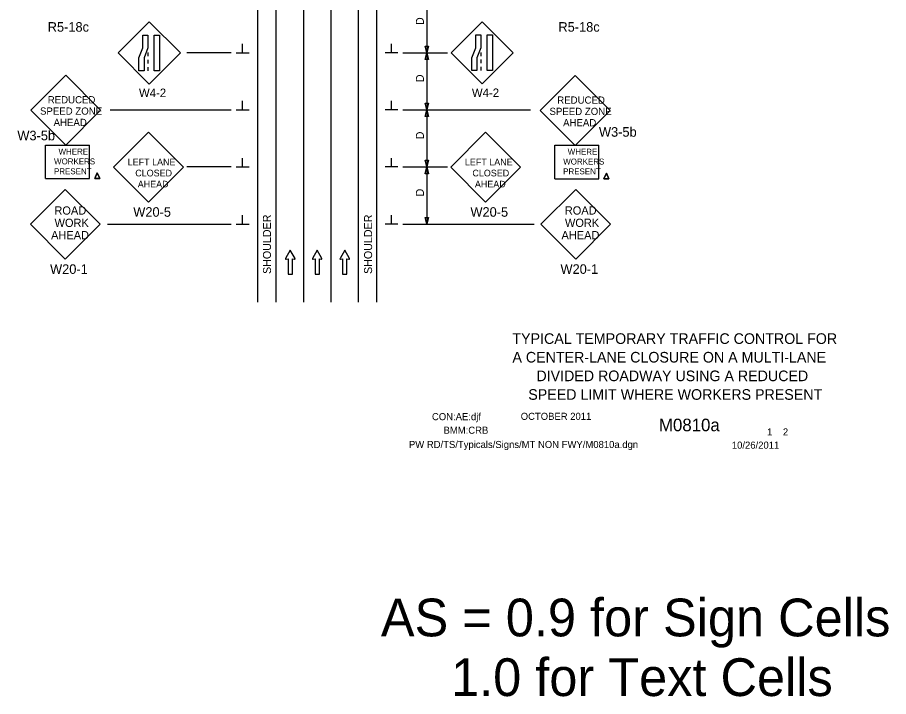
# Model space of a CAD drawing. Extents: x 16728 to 18482, y 5716 to 6919.
# Drawn here: x 16728 to 17490, y 5716 to 6311 of the extents above; entities that cross this region are included whole.
import ezdxf

# ---------------------------------------------------------------- set-up
doc = ezdxf.new("R2010")
doc.units = 0
for name, color, linetype in [('ALI_LEGAL_EX', 7, 'Continuous'), ('BORDER', 7, 'Continuous'), ('BORDER_SIGNAL_WO', 7, 'Continuous'), ('MT_SCRATCH_LEVEL_E', 7, 'Continuous'), ('PAVT_EDGE_EX', 7, 'Continuous'), ('TRAFFIC_SIGNS_PR', 7, 'Continuous'), ('TYPICAL_TEXT_DIMEN_PR', 7, 'Continuous')]:
    doc.layers.add(name, color=color, linetype=linetype)

msp = doc.modelspace()

# ---------------------------------------------------------------- linework, layer by layer
at = {"layer": 'ALI_LEGAL_EX'}
for p, q in [((16978.2, 6879.62), (16978.2, 6061.48)), ((17002.2, 6879.62), (17002.2, 6061.48))]:
    msp.add_line(p, q, dxfattribs=at)
for points in [[(16978.2, 6279.62), (16978.2, 6254.62)], [(17002.2, 6279.62), (17002.2, 6254.62)], [(16978.2, 6179.62), (16978.2, 6154.62)], [(17002.2, 6179.62), (17002.2, 6154.62)], [(16978.2, 6079.62), (16978.2, 6061.48)], [(17002.2, 6079.62), (17002.2, 6061.48)]]:
    msp.add_lwpolyline(points, dxfattribs=at)
at = {"layer": 'MT_SCRATCH_LEVEL_E'}
for p, q in [((16966.76, 6106.76), (16962.65, 6099.52)), ((16970.9, 6099.52), (16966.76, 6106.76)), ((16990.3, 6106.76), (16986.19, 6099.52)), ((16994.45, 6099.52), (16990.3, 6106.76)), ((17014.37, 6106.76), (17010.26, 6099.52)), ((17018.52, 6099.52), (17014.37, 6106.76)), ((16963.13, 6098.84), (16964.9, 6099.15)), ((16964.9, 6099.15), (16964.9, 6085.9)), ((16968.65, 6085.9), (16968.65, 6099.15)), ((16968.65, 6099.15), (16970.42, 6098.84)), ((16986.67, 6098.84), (16988.45, 6099.15)), ((16988.45, 6099.15), (16988.45, 6085.9)), ((16992.19, 6085.9), (16992.19, 6099.15)), ((16992.19, 6099.15), (16993.97, 6098.84)), ((17010.75, 6098.84), (17012.52, 6099.15)), ((17012.52, 6099.15), (17012.52, 6085.9)), ((17016.26, 6085.9), (17016.26, 6099.15)), ((17016.26, 6099.15), (17018.04, 6098.84)), ((16964.9, 6085.9), (16968.65, 6085.9)), ((16988.45, 6085.9), (16992.19, 6085.9)), ((17012.52, 6085.9), (17016.26, 6085.9))]:
    msp.add_line(p, q, dxfattribs=at)
for centre, start, end in [((16963.05, 6099.3), 150.42484, 279.96381), ((16970.49, 6099.3), 260.03619, 29.77312), ((16986.6, 6099.3), 150.42484, 279.96381), ((16994.04, 6099.3), 260.03619, 29.77312), ((17010.67, 6099.3), 150.42484, 279.96381), ((17018.11, 6099.3), 260.03619, 29.77312)]:
    msp.add_arc(centre, 0.463, start, end, dxfattribs=at)
at = {"layer": 'PAVT_EDGE_EX'}
for p, q in [((16938.2, 6879.62), (16938.2, 6061.48)), ((16954.2, 6879.62), (16954.2, 6061.48)), ((17026.2, 6879.62), (17026.2, 6061.48)), ((17042.2, 6879.62), (17042.2, 6061.48))]:
    msp.add_line(p, q, dxfattribs=at)
at = {"layer": 'TRAFFIC_SIGNS_PR'}
for p, q in [((16843.47, 6306.54), (16816.32, 6279.39)), ((16870.62, 6279.39), (16843.47, 6306.54)), ((17134.64, 6306.61), (17107.49, 6279.46)), ((17161.8, 6279.46), (17134.64, 6306.61)), ((16816.32, 6279.39), (16843.47, 6252.23)), ((16842.22, 6279.88), (16842.22, 6276.68)), ((16843.47, 6252.23), (16870.62, 6279.39)), ((17107.49, 6279.46), (17134.64, 6252.31)), ((17133.4, 6279.95), (17133.4, 6276.75)), ((17134.64, 6252.31), (17161.8, 6279.46)), ((16842.22, 6273.48), (16842.22, 6270.28)), ((17133.4, 6273.55), (17133.4, 6270.35)), ((16842.22, 6267.08), (16842.22, 6263.88)), ((17133.4, 6267.15), (17133.4, 6263.95)), ((16770.34, 6259.9), (16739.79, 6229.35)), ((16800.89, 6229.35), (16770.34, 6259.9)), ((17215.94, 6259.63), (17185.39, 6229.08)), ((17246.48, 6229.08), (17215.94, 6259.63)), ((16739.79, 6229.35), (16770.34, 6198.8)), ((16770.34, 6198.8), (16800.89, 6229.35)), ((17185.39, 6229.08), (17215.94, 6198.54)), ((17215.94, 6198.54), (17246.48, 6229.08)), ((16842.77, 6210.05), (16812.22, 6179.5)), ((16873.31, 6179.5), (16842.77, 6210.05)), ((17137.63, 6210.05), (17107.08, 6179.5)), ((17168.18, 6179.5), (17137.63, 6210.05)), ((16752.8, 6198.83), (16791.2, 6198.83)), ((16752.8, 6169.51), (16752.8, 6198.83)), ((16791.2, 6169.51), (16791.2, 6198.83)), ((17198.09, 6198.7), (17236.49, 6198.7)), ((17198.09, 6169.38), (17198.09, 6198.7)), ((17236.49, 6169.38), (17236.49, 6198.7)), ((16812.22, 6179.5), (16842.77, 6148.95)), ((16842.77, 6148.95), (16873.31, 6179.5)), ((17107.08, 6179.5), (17137.63, 6148.95)), ((17137.63, 6148.95), (17168.18, 6179.5)), ((16752.8, 6169.51), (16791.2, 6169.51)), ((17198.09, 6169.38), (17236.49, 6169.38)), ((16770.01, 6160.03), (16739.46, 6129.48)), ((16800.55, 6129.48), (16770.01, 6160.03)), ((17216.37, 6160.07), (17185.83, 6129.52)), ((17246.92, 6129.52), (17216.37, 6160.07)), ((16739.46, 6129.48), (16770.01, 6098.94)), ((16770.01, 6098.94), (16800.55, 6129.48)), ((17185.83, 6129.52), (17216.37, 6098.98)), ((17216.37, 6098.98), (17246.92, 6129.52))]:
    msp.add_line(p, q, dxfattribs=at)
for points in [[(16842.22, 6295.12), (16842.22, 6283.94), (16838.88, 6275.06), (16838.88, 6263.88), (16834.39, 6263.88), (16834.39, 6275.06), (16837.73, 6283.94), (16837.73, 6295.12)], [(16852.36, 6295.12), (16852.36, 6263.88), (16847.87, 6263.88), (16847.87, 6295.12)], [(17133.4, 6295.2), (17133.4, 6284.02), (17130.05, 6275.13), (17130.05, 6263.95), (17125.56, 6263.95), (17125.56, 6275.13), (17128.9, 6284.02), (17128.9, 6295.2)], [(17143.53, 6295.2), (17143.53, 6263.95), (17139.04, 6263.95), (17139.04, 6295.2)]]:
    msp.add_lwpolyline(points, close=True, dxfattribs=at)
for points in [[(16797.94, 6174.45), (16795.71, 6169.51)], [(16795.71, 6169.51), (16797.94, 6174.45)], [(16800.18, 6169.51), (16797.94, 6174.45)], [(16797.94, 6174.45), (16800.18, 6169.51)], [(17243.24, 6174.32), (17241, 6169.38)], [(17241, 6169.38), (17243.24, 6174.32)], [(17245.48, 6169.38), (17243.24, 6174.32)], [(17243.24, 6174.32), (17245.48, 6169.38)], [(16795.71, 6169.51), (16800.18, 6169.51)], [(16800.18, 6169.51), (16795.71, 6169.51)], [(17241, 6169.38), (17245.48, 6169.38)], [(17245.48, 6169.38), (17241, 6169.38)]]:
    msp.add_lwpolyline(points, dxfattribs=at)
at = {"layer": 'TYPICAL_TEXT_DIMEN_PR'}
for p, q in [((17086.2, 6329.63), (17086.2, 6279.63)), ((16925.07, 6279.63), (16925.07, 6287.42)), ((17055.32, 6279.63), (17055.32, 6287.42)), ((17086.2, 6279.63), (17084.63, 6285.5)), ((17084.63, 6285.5), (17086.2, 6285.5)), ((17086.2, 6285.5), (17087.77, 6285.5)), ((17087.77, 6285.5), (17086.2, 6279.63)), ((16915.2, 6279.63), (16876.2, 6279.63)), ((16919.45, 6279.63), (16930.7, 6279.63)), ((17060.95, 6279.63), (17049.7, 6279.63)), ((17065.2, 6279.63), (17104.2, 6279.63)), ((17084.63, 6273.77), (17086.2, 6279.63)), ((17086.2, 6279.63), (17086.2, 6229.63)), ((17086.2, 6279.63), (17087.77, 6273.77)), ((17086.2, 6273.77), (17084.63, 6273.77)), ((17087.77, 6273.77), (17086.2, 6273.77)), ((16925.07, 6229.63), (16925.07, 6237.42)), ((17055.32, 6229.63), (17055.32, 6237.42)), ((17086.2, 6229.63), (17084.63, 6235.5)), ((17084.63, 6235.5), (17086.2, 6235.5)), ((17086.2, 6235.5), (17087.77, 6235.5)), ((17087.77, 6235.5), (17086.2, 6229.63)), ((16809.18, 6229.63), (16915.2, 6229.63)), ((16919.45, 6229.63), (16930.7, 6229.63)), ((17060.95, 6229.63), (17049.7, 6229.63)), ((17065.2, 6229.63), (17176.98, 6229.63)), ((17084.63, 6223.77), (17086.2, 6229.63)), ((17086.2, 6229.63), (17086.2, 6179.63)), ((17086.2, 6229.63), (17087.77, 6223.77)), ((17086.2, 6223.77), (17084.63, 6223.77)), ((17087.77, 6223.77), (17086.2, 6223.77)), ((16925.07, 6179.63), (16925.07, 6187.42)), ((17055.32, 6179.63), (17055.32, 6187.42)), ((16915.2, 6179.63), (16876.2, 6179.63)), ((16919.45, 6179.63), (16930.7, 6179.63)), ((17060.95, 6179.63), (17049.7, 6179.63)), ((17065.2, 6179.63), (17104.2, 6179.63)), ((17086.2, 6179.63), (17084.63, 6185.5)), ((17084.63, 6185.5), (17086.2, 6185.5)), ((17084.63, 6173.77), (17086.2, 6179.63)), ((17086.2, 6185.5), (17087.77, 6185.5)), ((17087.77, 6185.5), (17086.2, 6179.63)), ((17086.2, 6179.63), (17086.2, 6129.63)), ((17086.2, 6179.63), (17087.77, 6173.77)), ((17086.2, 6173.77), (17084.63, 6173.77)), ((17087.77, 6173.77), (17086.2, 6173.77)), ((16925.07, 6129.63), (16925.07, 6137.42)), ((17055.32, 6129.63), (17055.32, 6137.42)), ((17086.2, 6129.63), (17084.63, 6135.5)), ((17084.63, 6135.5), (17086.2, 6135.5)), ((17086.2, 6135.5), (17087.77, 6135.5)), ((17087.77, 6135.5), (17086.2, 6129.63)), ((16806.95, 6129.63), (16915.2, 6129.63)), ((16919.45, 6129.63), (16930.7, 6129.63)), ((17060.95, 6129.63), (17049.7, 6129.63)), ((17065.2, 6129.63), (17180.14, 6129.63))]:
    msp.add_line(p, q, dxfattribs=at)

# ---------------------------------------------------------------- texts
at = {"layer": 'BORDER'}
for s, p in [('TYPICAL TEMPORARY TRAFFIC CONTROL FOR', (17161.04, 6024.8)), ('A CENTER-LANE CLOSURE ON A MULTI-LANE', (17161.06, 6008.5)), ('DIVIDED ROADWAY USING A REDUCED', (17182.02, 5992.2)), ('SPEED LIMIT WHERE WORKERS PRESENT', (17174.92, 5975.9))]:
    msp.add_text(s, height=9.3, dxfattribs=at).set_placement(p)
at = {"layer": 'BORDER_SIGNAL_WO'}
for s, height, p in [('CON:AE:djf', 6.2, (17090.69, 5958.06)), ('    OCTOBER 2011    ', 6.2, (17159.08, 5958.34)), ('    M0810a   ', 11, (17272.86, 5948.38)), ('BMM:CRB   ', 6.2, (17100.81, 5946.17)), (' 1    2 ', 6.2, (17381.45, 5944.7)), ('PW RD/TS/Typicals/Signs/MT NON FWY/M0810a.dgn    ', 6.2, (17070.55, 5933.71)), ('10/26/2011    ', 6.2, (17352.93, 5933.13)), ('AS = 0.9 for Sign Cells', 33.0301, (17046.01, 5768.88)), ('     1.0 for Text Cells', 33.0301, (17046.01, 5716.65))]:
    msp.add_text(s, height=height, dxfattribs=at).set_placement(p)
at = {"layer": 'TRAFFIC_SIGNS_PR'}
for s, height, p in [('R5-18c', 8.37, (16754.65, 6298.02)), ('R5-18c', 8.37, (17201.28, 6298.02)), ('W4-2', 7.44, (16834.43, 6240.79)), ('W4-2', 7.44, (17125.6, 6240.87)), ('REDUCED', 6.3, (16754.65, 6235.32)), ('REDUCED', 6.3, (17200.25, 6235.05)), ('SPEED ZONE', 6.3, (16747.9, 6225.42)), ('SPEED ZONE', 6.3, (17193.49, 6225.15)), ('AHEAD', 6.3, (16759.78, 6215.52)), ('AHEAD', 6.3, (17205.37, 6215.25)), ('W3-5b', 8.37, (16728.09, 6202.96)), ('W3-5b', 8.37, (17236.74, 6206.11)), ('WHERE', 5.2, (16764.11, 6190.51)), ('WHERE', 5.2, (17209.4, 6190.38)), ('WORKERS', 5.2, (16760.18, 6181.91)), ('LEFT LANE', 5.85, (16824.63, 6181.07)), ('LEFT LANE', 5.85, (17119.49, 6181.07)), ('WORKERS', 5.2, (17205.47, 6181.78)), ('PRESENT', 5.2, (16760.11, 6173.31)), ('CLOSED', 5.85, (16831.19, 6171.39)), ('CLOSED', 5.85, (17126.06, 6171.39)), ('PRESENT', 5.2, (17205.41, 6173.18)), ('AHEAD', 5.85, (16833.38, 6161.72)), ('AHEAD', 5.85, (17128.24, 6161.72)), ('ROAD', 7.2, (16760.49, 6137.96)), ('W20-5', 8.37, (16829.46, 6136.08)), ('W20-5', 8.37, (17124.32, 6136.08)), ('ROAD', 7.2, (17206.86, 6138)), ('WORK', 7.2, (16760.61, 6127.16)), ('WORK', 7.2, (17206.98, 6127.2)), ('AHEAD', 7.2, (16757.59, 6116.36)), ('AHEAD', 7.2, (17203.95, 6116.4)), ('W20-1', 8.37, (16756.7, 6086.07)), ('W20-1', 8.37, (17203.07, 6086.11))]:
    msp.add_text(s, height=height, dxfattribs=at).set_placement(p)
at = {"layer": 'TYPICAL_TEXT_DIMEN_PR'}
for s, p in [('D', (17083.64, 6303.85)), ('D', (17083.64, 6253.85)), ('D', (17083.64, 6203.85)), ('D', (17083.64, 6153.85)), ('SHOULDER', (16949.88, 6086.01)), ('SHOULDER', (17038.31, 6086.01))]:
    msp.add_text(s, height=7, rotation=90, dxfattribs=at).set_placement(p)

doc.saveas('drawing.dxf')
